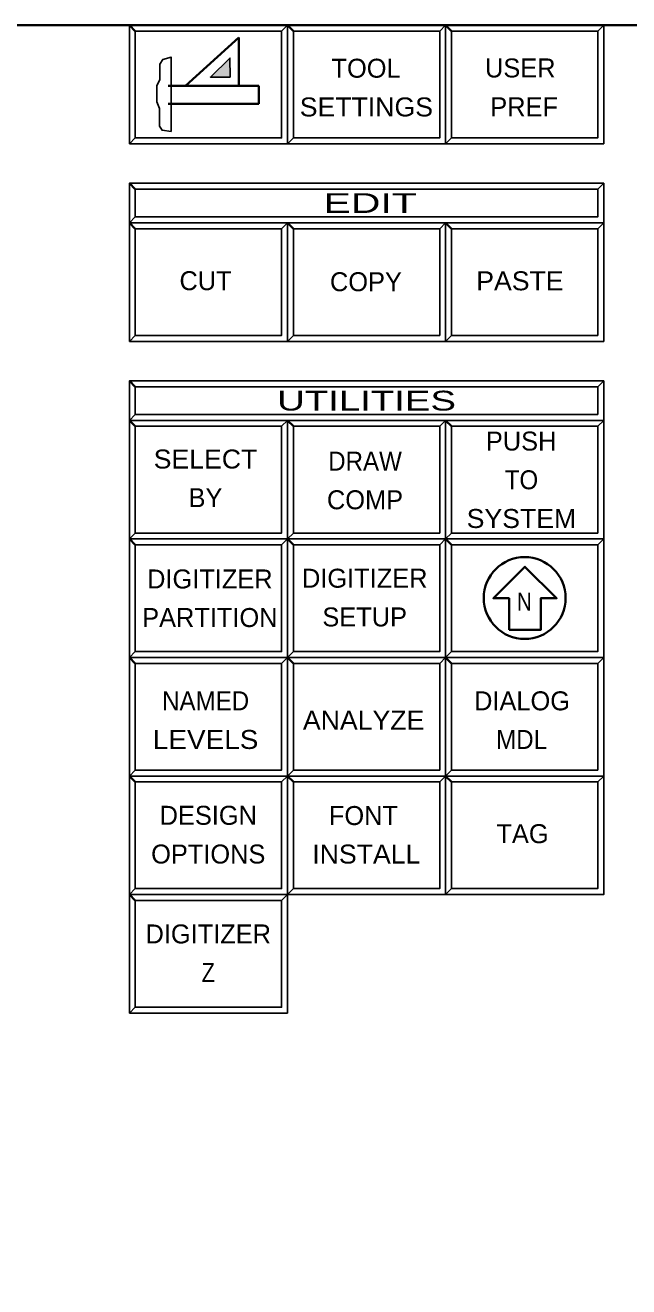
# Model space of a CAD drawing. Extents: x 95906.9 to 95918.9, y 90964.8 to 90972.9.
# Drawn here: x 95914.669 to 95916.196, y 90969.669 to 90972.862 of the extents above; entities that cross this region are included whole.
import ezdxf
from ezdxf.enums import TextEntityAlignment as Align

# ---------------------------------------------------------------- set-up
doc = ezdxf.new("R2010")
doc.units = 0
doc.header["$LTSCALE"] = 0.019
for name, color, linetype, lineweight in [('1', 7, 'Continuous', 25), ('11', 7, 'Continuous', 25), ('18', 7, 'Continuous', 25), ('2', 7, 'Continuous', 13), ('3', 7, 'Continuous', 25), ('4', 7, 'Continuous', 35), ('6', 7, 'Continuous', 35), ('7', 7, 'Continuous', 35)]:
    doc.layers.add(name, color=color, linetype=linetype, lineweight=lineweight)

msp = doc.modelspace()

# ---------------------------------------------------------------- hatches: boundary and pattern name
at = {"layer": '6'}
msp.add_hatch(color=256, dxfattribs=at).paths.add_polyline_path([(95915.1869, 90972.7304), (95915.1866, 90972.7786), (95915.1375, 90972.7306)])

# ---------------------------------------------------------------- linework, layer by layer
at = {"layer": '1'}
for points in [[(95914.9323, 90972.5617), (95915.3323, 90972.5617), (95915.3323, 90972.8617), (95914.9323, 90972.8617)], [(95915.3323, 90972.5617), (95915.7323, 90972.5617), (95915.7323, 90972.8617), (95915.3323, 90972.8617)], [(95915.7323, 90972.5617), (95916.1323, 90972.5617), (95916.1323, 90972.8617), (95915.7323, 90972.8617)], [(95914.9323, 90972.3617), (95916.1323, 90972.3617), (95916.1323, 90972.4617), (95914.9323, 90972.4617)], [(95914.9323, 90972.0617), (95915.3323, 90972.0617), (95915.3323, 90972.3617), (95914.9323, 90972.3617)], [(95915.3323, 90972.0617), (95915.7323, 90972.0617), (95915.7323, 90972.3617), (95915.3323, 90972.3617)], [(95915.7323, 90972.0617), (95916.1323, 90972.0617), (95916.1323, 90972.3617), (95915.7323, 90972.3617)], [(95914.9323, 90971.8617), (95916.1323, 90971.8617), (95916.1323, 90971.9617), (95914.9323, 90971.9617)], [(95914.9323, 90971.5617), (95915.3323, 90971.5617), (95915.3323, 90971.8617), (95914.9323, 90971.8617)], [(95915.3323, 90971.5617), (95915.7323, 90971.5617), (95915.7323, 90971.8617), (95915.3323, 90971.8617)], [(95915.7323, 90971.5617), (95916.1323, 90971.5617), (95916.1323, 90971.8617), (95915.7323, 90971.8617)], [(95914.9323, 90971.2617), (95915.3323, 90971.2617), (95915.3323, 90971.5617), (95914.9323, 90971.5617)], [(95915.3323, 90971.2617), (95915.7323, 90971.2617), (95915.7323, 90971.5617), (95915.3323, 90971.5617)], [(95915.7323, 90971.2617), (95916.1323, 90971.2617), (95916.1323, 90971.5617), (95915.7323, 90971.5617)], [(95914.9323, 90970.9617), (95915.3323, 90970.9617), (95915.3323, 90971.2617), (95914.9323, 90971.2617)], [(95915.3323, 90970.9617), (95915.7323, 90970.9617), (95915.7323, 90971.2617), (95915.3323, 90971.2617)], [(95915.7323, 90970.9617), (95916.1323, 90970.9617), (95916.1323, 90971.2617), (95915.7323, 90971.2617)], [(95914.9323, 90970.6617), (95915.3323, 90970.6617), (95915.3323, 90970.9617), (95914.9323, 90970.9617)], [(95915.3323, 90970.6617), (95915.7323, 90970.6617), (95915.7323, 90970.9617), (95915.3323, 90970.9617)], [(95915.7323, 90970.6617), (95916.1323, 90970.6617), (95916.1323, 90970.9617), (95915.7323, 90970.9617)], [(95914.9323, 90970.3617), (95915.3323, 90970.3617), (95915.3323, 90970.6617), (95914.9323, 90970.6617)]]:
    msp.add_lwpolyline(points, close=True, dxfattribs=at)
at = {"layer": '11'}
for points in [[(95914.9473, 90972.5767), (95915.3173, 90972.5767), (95915.3173, 90972.8467), (95914.9473, 90972.8467)], [(95915.3473, 90972.5767), (95915.7173, 90972.5767), (95915.7173, 90972.8467), (95915.3473, 90972.8467)], [(95915.7473, 90972.5767), (95916.1173, 90972.5767), (95916.1173, 90972.8467), (95915.7473, 90972.8467)], [(95914.9473, 90972.0767), (95915.3173, 90972.0767), (95915.3173, 90972.3467), (95914.9473, 90972.3467)], [(95915.3473, 90972.0767), (95915.7173, 90972.0767), (95915.7173, 90972.3467), (95915.3473, 90972.3467)], [(95915.7473, 90972.0767), (95916.1173, 90972.0767), (95916.1173, 90972.3467), (95915.7473, 90972.3467)], [(95914.9473, 90971.5767), (95915.3173, 90971.5767), (95915.3173, 90971.8467), (95914.9473, 90971.8467)], [(95915.3473, 90971.5767), (95915.7173, 90971.5767), (95915.7173, 90971.8467), (95915.3473, 90971.8467)], [(95915.7473, 90971.5767), (95916.1173, 90971.5767), (95916.1173, 90971.8467), (95915.7473, 90971.8467)], [(95914.9473, 90971.2767), (95915.3173, 90971.2767), (95915.3173, 90971.5467), (95914.9473, 90971.5467)], [(95915.3473, 90971.2767), (95915.7173, 90971.2767), (95915.7173, 90971.5467), (95915.3473, 90971.5467)], [(95915.7473, 90971.2767), (95916.1173, 90971.2767), (95916.1173, 90971.5467), (95915.7473, 90971.5467)], [(95914.9473, 90970.9767), (95915.3173, 90970.9767), (95915.3173, 90971.2467), (95914.9473, 90971.2467)], [(95915.3473, 90970.9767), (95915.7173, 90970.9767), (95915.7173, 90971.2467), (95915.3473, 90971.2467)], [(95915.7473, 90970.9767), (95916.1173, 90970.9767), (95916.1173, 90971.2467), (95915.7473, 90971.2467)], [(95914.9473, 90970.6767), (95915.3173, 90970.6767), (95915.3173, 90970.9467), (95914.9473, 90970.9467)], [(95915.3473, 90970.6767), (95915.7173, 90970.6767), (95915.7173, 90970.9467), (95915.3473, 90970.9467)], [(95915.7473, 90970.6767), (95916.1173, 90970.6767), (95916.1173, 90970.9467), (95915.7473, 90970.9467)], [(95914.9473, 90970.3767), (95915.3173, 90970.3767), (95915.3173, 90970.6467), (95914.9473, 90970.6467)]]:
    msp.add_lwpolyline(points, close=True, dxfattribs=at)
at = {"layer": '18'}
for points in [[(95914.9473, 90972.3767), (95916.1173, 90972.3767), (95916.1173, 90972.4467), (95914.9473, 90972.4467)], [(95914.9473, 90971.8767), (95916.1173, 90971.8767), (95916.1173, 90971.9467), (95914.9473, 90971.9467)]]:
    msp.add_lwpolyline(points, close=True, dxfattribs=at)
at = {"layer": '2'}
for points in [[(95914.9323, 90972.8617), (95914.9323, 90972.5617), (95914.9473, 90972.5767), (95914.9473, 90972.8467), (95915.3173, 90972.8467), (95915.3323, 90972.8617)], [(95915.3323, 90972.8617), (95915.3323, 90972.5617), (95915.3473, 90972.5767), (95915.3473, 90972.8467), (95915.7173, 90972.8467), (95915.7323, 90972.8617)], [(95915.7323, 90972.8617), (95915.7323, 90972.5617), (95915.7473, 90972.5767), (95915.7473, 90972.8467), (95916.1173, 90972.8467), (95916.1323, 90972.8617)], [(95914.9323, 90972.4617), (95914.9323, 90972.3617), (95914.9473, 90972.3767), (95914.9473, 90972.4467), (95916.1173, 90972.4467), (95916.1323, 90972.4617)], [(95914.9323, 90972.3617), (95914.9323, 90972.0617), (95914.9473, 90972.0767), (95914.9473, 90972.3467), (95915.3173, 90972.3467), (95915.3323, 90972.3617)], [(95915.3323, 90972.3617), (95915.3323, 90972.0617), (95915.3473, 90972.0767), (95915.3473, 90972.3467), (95915.7173, 90972.3467), (95915.7323, 90972.3617)], [(95915.7323, 90972.3617), (95915.7323, 90972.0617), (95915.7473, 90972.0767), (95915.7473, 90972.3467), (95916.1173, 90972.3467), (95916.1323, 90972.3617)], [(95914.9323, 90971.9617), (95914.9323, 90971.8617), (95914.9473, 90971.8767), (95914.9473, 90971.9467), (95916.1173, 90971.9467), (95916.1323, 90971.9617)], [(95914.9323, 90971.8617), (95914.9323, 90971.5617), (95914.9473, 90971.5767), (95914.9473, 90971.8467), (95915.3173, 90971.8467), (95915.3323, 90971.8617)], [(95915.3323, 90971.8617), (95915.3323, 90971.5617), (95915.3473, 90971.5767), (95915.3473, 90971.8467), (95915.7173, 90971.8467), (95915.7323, 90971.8617)], [(95915.7323, 90971.8617), (95915.7323, 90971.5617), (95915.7473, 90971.5767), (95915.7473, 90971.8467), (95916.1173, 90971.8467), (95916.1323, 90971.8617)], [(95914.9323, 90971.5617), (95914.9323, 90971.2617), (95914.9473, 90971.2767), (95914.9473, 90971.5467), (95915.3173, 90971.5467), (95915.3323, 90971.5617)], [(95915.3323, 90971.5617), (95915.3323, 90971.2617), (95915.3473, 90971.2767), (95915.3473, 90971.5467), (95915.7173, 90971.5467), (95915.7323, 90971.5617)], [(95915.7323, 90971.5617), (95915.7323, 90971.2617), (95915.7473, 90971.2767), (95915.7473, 90971.5467), (95916.1173, 90971.5467), (95916.1323, 90971.5617)], [(95914.9323, 90971.2617), (95914.9323, 90970.9617), (95914.9473, 90970.9767), (95914.9473, 90971.2467), (95915.3173, 90971.2467), (95915.3323, 90971.2617)], [(95915.3323, 90971.2617), (95915.3323, 90970.9617), (95915.3473, 90970.9767), (95915.3473, 90971.2467), (95915.7173, 90971.2467), (95915.7323, 90971.2617)], [(95915.7323, 90971.2617), (95915.7323, 90970.9617), (95915.7473, 90970.9767), (95915.7473, 90971.2467), (95916.1173, 90971.2467), (95916.1323, 90971.2617)], [(95914.9323, 90970.9617), (95914.9323, 90970.6617), (95914.9473, 90970.6767), (95914.9473, 90970.9467), (95915.3173, 90970.9467), (95915.3323, 90970.9617)], [(95915.3323, 90970.9617), (95915.3323, 90970.6617), (95915.3473, 90970.6767), (95915.3473, 90970.9467), (95915.7173, 90970.9467), (95915.7323, 90970.9617)], [(95915.7323, 90970.9617), (95915.7323, 90970.6617), (95915.7473, 90970.6767), (95915.7473, 90970.9467), (95916.1173, 90970.9467), (95916.1323, 90970.9617)], [(95914.9323, 90970.6617), (95914.9323, 90970.3617), (95914.9473, 90970.3767), (95914.9473, 90970.6467), (95915.3173, 90970.6467), (95915.3323, 90970.6617)]]:
    msp.add_lwpolyline(points, close=True, dxfattribs=at)
at = {"layer": '3'}
for points in [[(95914.9323, 90972.5617), (95915.3323, 90972.5617), (95915.3323, 90972.8617), (95915.3173, 90972.8467), (95915.3173, 90972.5767), (95914.9473, 90972.5767)], [(95915.3323, 90972.5617), (95915.7323, 90972.5617), (95915.7323, 90972.8617), (95915.7173, 90972.8467), (95915.7173, 90972.5767), (95915.3473, 90972.5767)], [(95915.7323, 90972.5617), (95916.1323, 90972.5617), (95916.1323, 90972.8617), (95916.1173, 90972.8467), (95916.1173, 90972.5767), (95915.7473, 90972.5767)], [(95914.9323, 90972.3617), (95916.1323, 90972.3617), (95916.1323, 90972.4617), (95916.1173, 90972.4467), (95916.1173, 90972.3767), (95914.9473, 90972.3767)], [(95914.9323, 90972.0617), (95915.3323, 90972.0617), (95915.3323, 90972.3617), (95915.3173, 90972.3467), (95915.3173, 90972.0767), (95914.9473, 90972.0767)], [(95915.3323, 90972.0617), (95915.7323, 90972.0617), (95915.7323, 90972.3617), (95915.7173, 90972.3467), (95915.7173, 90972.0767), (95915.3473, 90972.0767)], [(95915.7323, 90972.0617), (95916.1323, 90972.0617), (95916.1323, 90972.3617), (95916.1173, 90972.3467), (95916.1173, 90972.0767), (95915.7473, 90972.0767)], [(95914.9323, 90971.8617), (95916.1323, 90971.8617), (95916.1323, 90971.9617), (95916.1173, 90971.9467), (95916.1173, 90971.8767), (95914.9473, 90971.8767)], [(95914.9323, 90971.5617), (95915.3323, 90971.5617), (95915.3323, 90971.8617), (95915.3173, 90971.8467), (95915.3173, 90971.5767), (95914.9473, 90971.5767)], [(95915.3323, 90971.5617), (95915.7323, 90971.5617), (95915.7323, 90971.8617), (95915.7173, 90971.8467), (95915.7173, 90971.5767), (95915.3473, 90971.5767)], [(95915.7323, 90971.5617), (95916.1323, 90971.5617), (95916.1323, 90971.8617), (95916.1173, 90971.8467), (95916.1173, 90971.5767), (95915.7473, 90971.5767)], [(95914.9323, 90971.2617), (95915.3323, 90971.2617), (95915.3323, 90971.5617), (95915.3173, 90971.5467), (95915.3173, 90971.2767), (95914.9473, 90971.2767)], [(95915.3323, 90971.2617), (95915.7323, 90971.2617), (95915.7323, 90971.5617), (95915.7173, 90971.5467), (95915.7173, 90971.2767), (95915.3473, 90971.2767)], [(95915.7323, 90971.2617), (95916.1323, 90971.2617), (95916.1323, 90971.5617), (95916.1173, 90971.5467), (95916.1173, 90971.2767), (95915.7473, 90971.2767)], [(95914.9323, 90970.9617), (95915.3323, 90970.9617), (95915.3323, 90971.2617), (95915.3173, 90971.2467), (95915.3173, 90970.9767), (95914.9473, 90970.9767)], [(95915.3323, 90970.9617), (95915.7323, 90970.9617), (95915.7323, 90971.2617), (95915.7173, 90971.2467), (95915.7173, 90970.9767), (95915.3473, 90970.9767)], [(95915.7323, 90970.9617), (95916.1323, 90970.9617), (95916.1323, 90971.2617), (95916.1173, 90971.2467), (95916.1173, 90970.9767), (95915.7473, 90970.9767)], [(95914.9323, 90970.6617), (95915.3323, 90970.6617), (95915.3323, 90970.9617), (95915.3173, 90970.9467), (95915.3173, 90970.6767), (95914.9473, 90970.6767)], [(95915.3323, 90970.6617), (95915.7323, 90970.6617), (95915.7323, 90970.9617), (95915.7173, 90970.9467), (95915.7173, 90970.6767), (95915.3473, 90970.6767)], [(95915.7323, 90970.6617), (95916.1323, 90970.6617), (95916.1323, 90970.9617), (95916.1173, 90970.9467), (95916.1173, 90970.6767), (95915.7473, 90970.6767)], [(95914.9323, 90970.3617), (95915.3323, 90970.3617), (95915.3323, 90970.6617), (95915.3173, 90970.6467), (95915.3173, 90970.3767), (95914.9473, 90970.3767)]]:
    msp.add_lwpolyline(points, close=True, dxfattribs=at)
at = {"layer": '4'}
for p, q in [((95914.9473, 90972.8467), (95914.9323, 90972.8617)), ((95915.3473, 90972.8467), (95915.3323, 90972.8617)), ((95915.7473, 90972.8467), (95915.7323, 90972.8617)), ((95914.9473, 90972.4467), (95914.9323, 90972.4617)), ((95914.9473, 90972.3467), (95914.9323, 90972.3617)), ((95915.3473, 90972.3467), (95915.3323, 90972.3617)), ((95915.7473, 90972.3467), (95915.7323, 90972.3617)), ((95914.9473, 90971.9467), (95914.9323, 90971.9617)), ((95914.9473, 90971.8467), (95914.9323, 90971.8617)), ((95915.3473, 90971.8467), (95915.3323, 90971.8617)), ((95915.7473, 90971.8467), (95915.7323, 90971.8617)), ((95914.9473, 90971.5467), (95914.9323, 90971.5617)), ((95915.3473, 90971.5467), (95915.3323, 90971.5617)), ((95915.7473, 90971.5467), (95915.7323, 90971.5617)), ((95914.9473, 90971.2467), (95914.9323, 90971.2617)), ((95915.3473, 90971.2467), (95915.3323, 90971.2617)), ((95915.7473, 90971.2467), (95915.7323, 90971.2617)), ((95914.9473, 90970.9467), (95914.9323, 90970.9617)), ((95915.3473, 90970.9467), (95915.3323, 90970.9617)), ((95915.7473, 90970.9467), (95915.7323, 90970.9617)), ((95914.9473, 90970.6467), (95914.9323, 90970.6617))]:
    msp.add_line(p, q, dxfattribs=at)
at = {"layer": '6'}
for p, q in [((95915.0746, 90972.7083), (95915.2093, 90972.831)), ((95915.2096, 90972.7084), (95915.2093, 90972.831)), ((95915.0305, 90972.7083), (95915.2594, 90972.7083)), ((95915.2594, 90972.6632), (95915.2594, 90972.7083)), ((95915.0306, 90972.6632), (95915.2594, 90972.6632))]:
    msp.add_line(p, q, dxfattribs=at)
at = {"layer": '6', "lineweight": 25}
for points in [[(95915.0015, 90972.668), (95915.0087, 90972.6509), (95915.0087, 90972.6059), (95915.015, 90972.596), (95915.0379, 90972.593), (95915.0379, 90972.7813), (95915.0168, 90972.7752), (95915.0096, 90972.7635), (95915.0096, 90972.7238), (95915.0015, 90972.7094)], [(95915.1869, 90972.7304), (95915.1866, 90972.7786), (95915.1375, 90972.7306)]]:
    msp.add_lwpolyline(points, close=True, dxfattribs=at)
at = {"layer": '6'}
msp.add_lwpolyline([(95915.893, 90971.3314), (95915.893, 90971.4114), (95915.853, 90971.4114), (95915.933, 90971.4914), (95916.013, 90971.4114), (95915.973, 90971.4114), (95915.973, 90971.3314)], close=True, dxfattribs=at)
msp.add_circle((95915.9323, 90971.4122), 0.1036, dxfattribs=at)
at = {"layer": '7'}
msp.add_lwpolyline([(95906.8548, 90972.8617), (95918.8548, 90972.8617), (95918.8548, 90964.7617), (95906.8548, 90964.7617)], close=True, dxfattribs=at)

# ---------------------------------------------------------------- texts
at = {"layer": '6'}
for s, p in [('USER', (95915.9211, 90972.7296)), ('TOOL', (95915.5311, 90972.7289)), ('PREF', (95915.9309, 90972.6313)), ('CUT', (95915.125, 90972.1912)), ('COPY', (95915.5307, 90972.1886)), ('PUSH', (95915.9233, 90971.7854)), ('BY', (95915.1248, 90971.6421)), ('COMP', (95915.5284, 90971.6368)), ('DIGITIZER', (95915.1359, 90971.4364)), ('DIGITIZER', (95915.5277, 90971.4383)), ('PARTITION', (95915.1359, 90971.3388)), ('SETUP', (95915.5276, 90971.3403)), ('DIALOG', (95915.9256, 90971.128)), ('DESIGN', (95915.1319, 90970.8383)), ('FONT', (95915.5244, 90970.8377)), ('TAG', (95915.9268, 90970.7918)), ('OPTIONS', (95915.1319, 90970.7403)), ('DIGITIZER', (95915.1319, 90970.5381))]:
    msp.add_text(s, height=0.048, dxfattribs=at).set_placement(p, align=Align.CENTER)
for s, height, width, p in [('SETTINGS', 0.048, 1.05, (95915.5318, 90972.6309)), ('PASTE', 0.048, 1.05, (95915.9202, 90972.1909)), ('SELECT', 0.048, 1.05, (95915.1249, 90971.7399)), ('DRAW', 0.048, 0.95, (95915.5284, 90971.7346)), ('TO', 0.048, 0.95, (95915.9241, 90971.6874)), ('SYSTEM', 0.048, 1.05, (95915.9241, 90971.5894)), ('N', 0.045, 0.85, (95915.9315, 90971.3804)), ('NAMED', 0.048, 0.95, (95915.1252, 90971.128)), ('ANALYZE', 0.048, 1.05, (95915.5249, 90971.0791)), ('LEVELS', 0.048, 1.1, (95915.1252, 90971.0302)), ('MDL', 0.048, 0.95, (95915.9244, 90971.0302)), ('INSTALL', 0.048, 1.05, (95915.5317, 90970.7402)), ('Z', 0.048, 0.85, (95915.1319, 90970.4405))]:
    msp.add_text(s, height=height, dxfattribs=dict(at, width=width)).set_placement(p, align=Align.CENTER)
at = {"layer": '7'}
for s, height, width, p in [('       EDIT       ', 0.05, 1.55, (95915.5415, 90972.3867)), ('       UTILITIES       ', 0.04999, 1.45, (95915.5323, 90971.8867))]:
    msp.add_text(s, height=height, dxfattribs=dict(at, width=width)).set_placement(p, align=Align.CENTER)

doc.saveas('drawing.dxf')
